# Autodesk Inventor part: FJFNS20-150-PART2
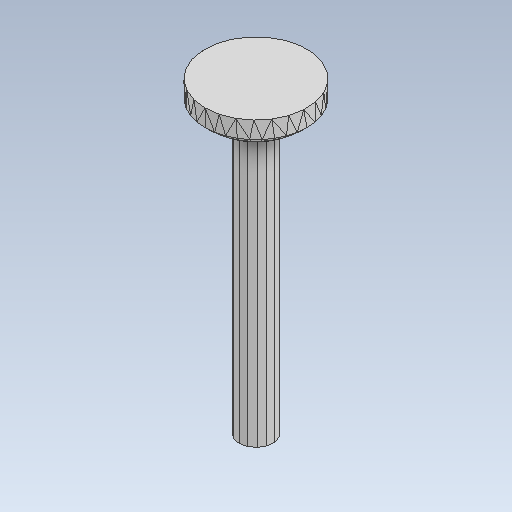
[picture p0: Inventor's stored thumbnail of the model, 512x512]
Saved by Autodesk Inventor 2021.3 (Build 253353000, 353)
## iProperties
Created: 2022-02
Part Number: FJFNS20-150-PART2
Material: 一般
Document SubType Name: Modeling
Designer: kengo
Density: 1 g/cm^3
Appearance: 既定
Author: kengo
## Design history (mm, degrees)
feature "FJFNS20-150-PART2"
node "ソリッド1"
